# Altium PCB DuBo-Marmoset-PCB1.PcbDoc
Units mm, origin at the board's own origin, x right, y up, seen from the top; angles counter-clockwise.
Board outline 13.9 x 25.08 mm, 4 copper layers (Top Signal, Layer 2 - VCC, Layer 3 - GND, Bottom Layer), stack 0.532 mm thick; 7 components, 33 nets, 180 pads, 39 vias.
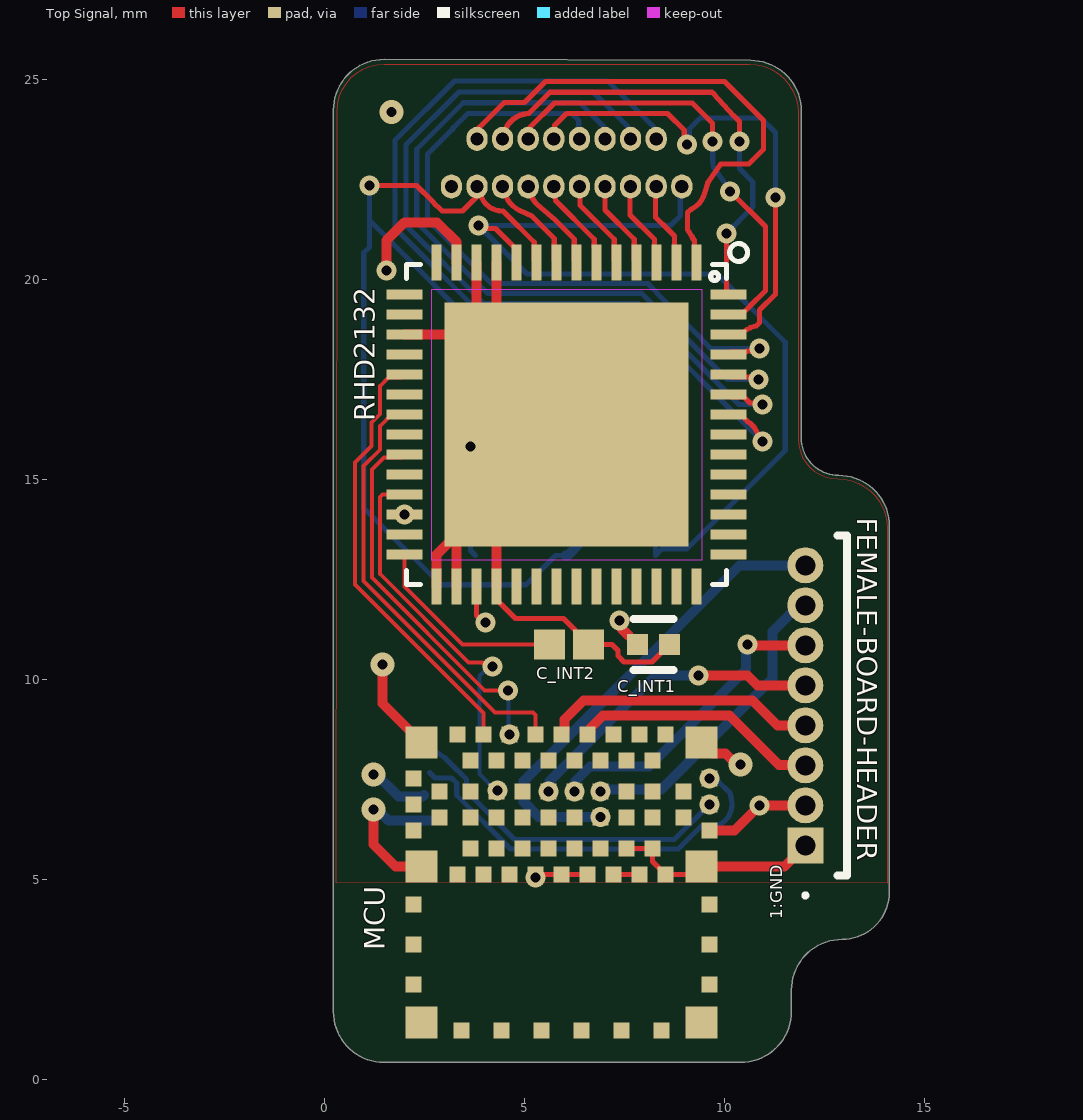
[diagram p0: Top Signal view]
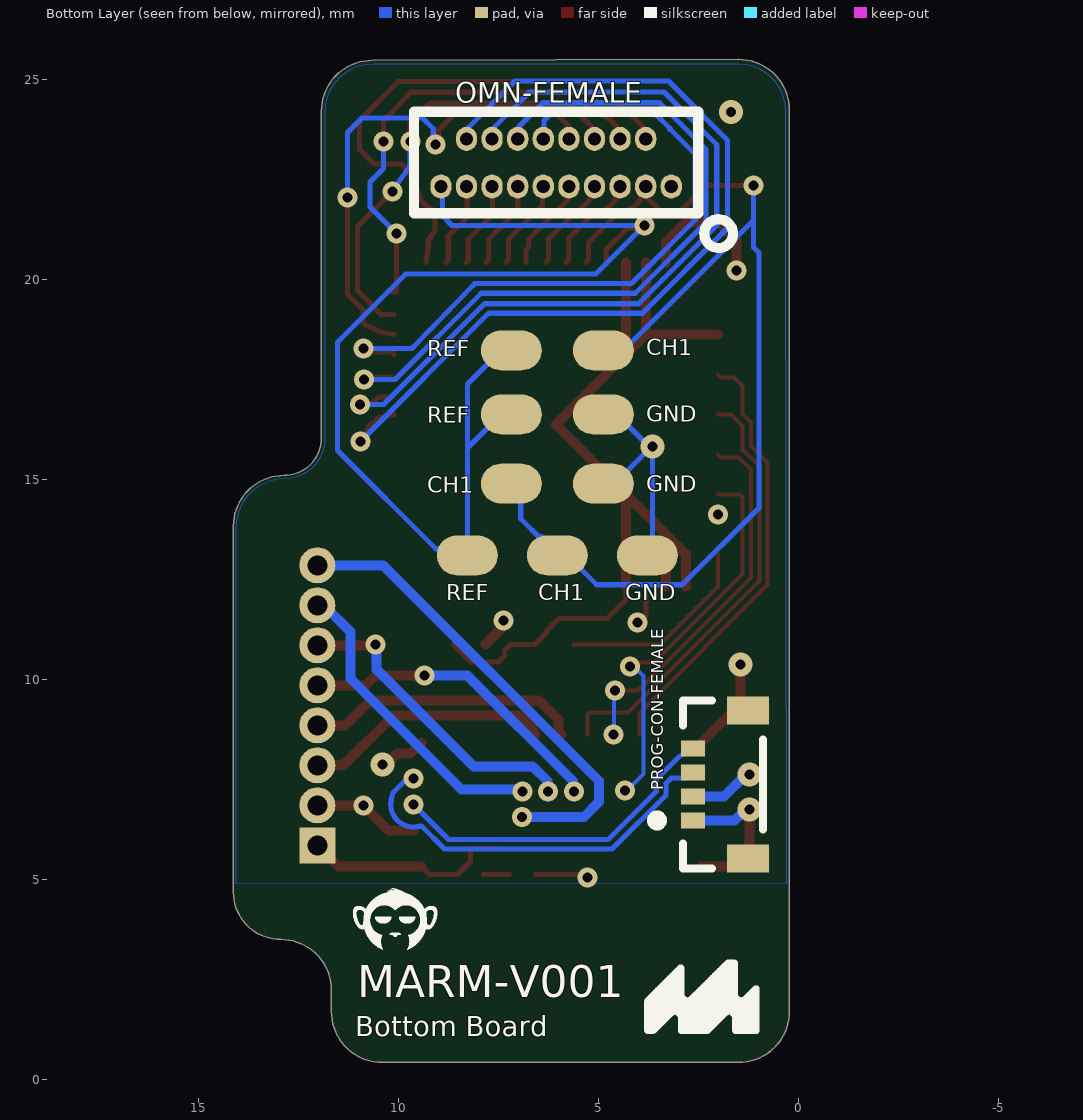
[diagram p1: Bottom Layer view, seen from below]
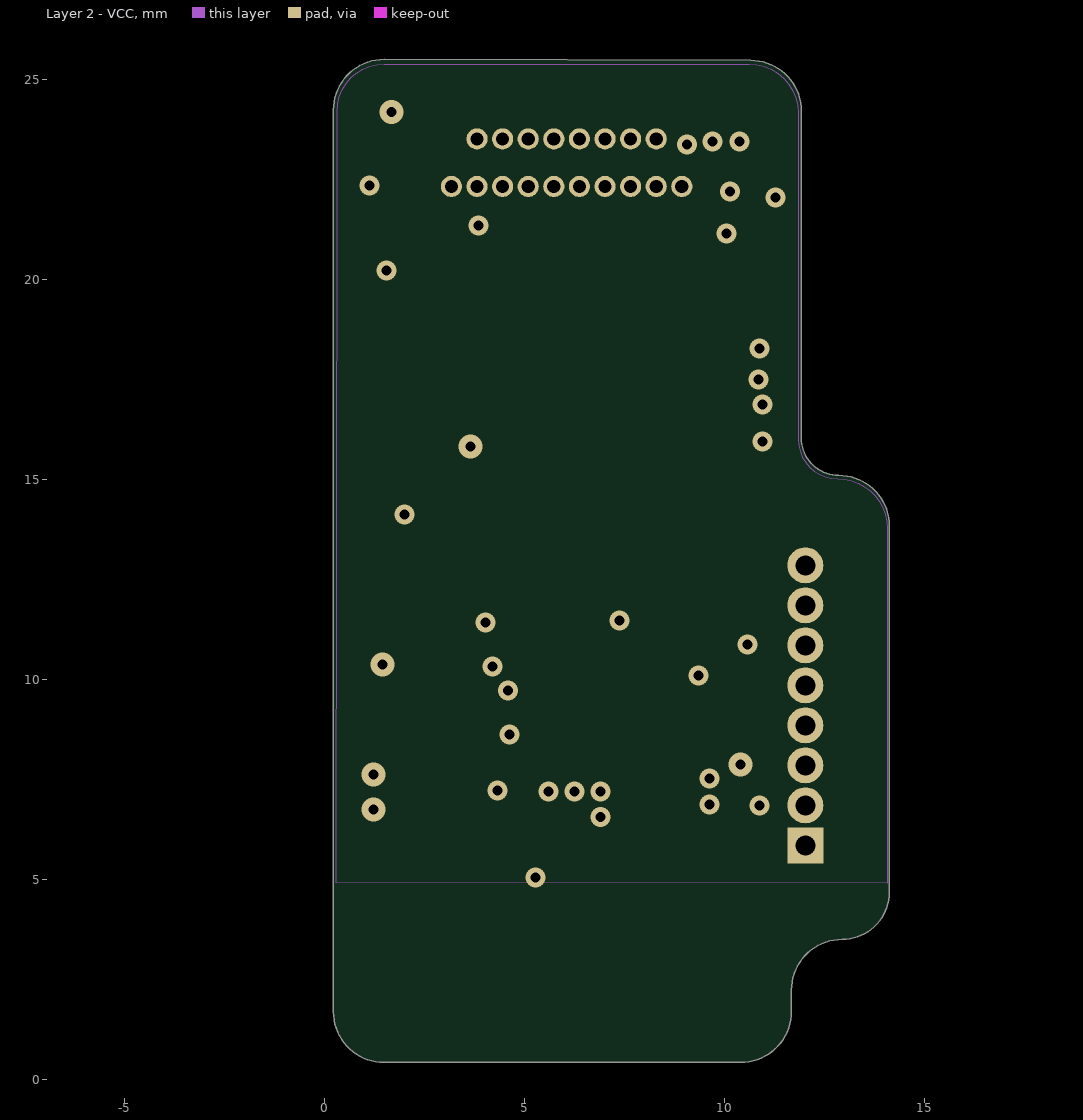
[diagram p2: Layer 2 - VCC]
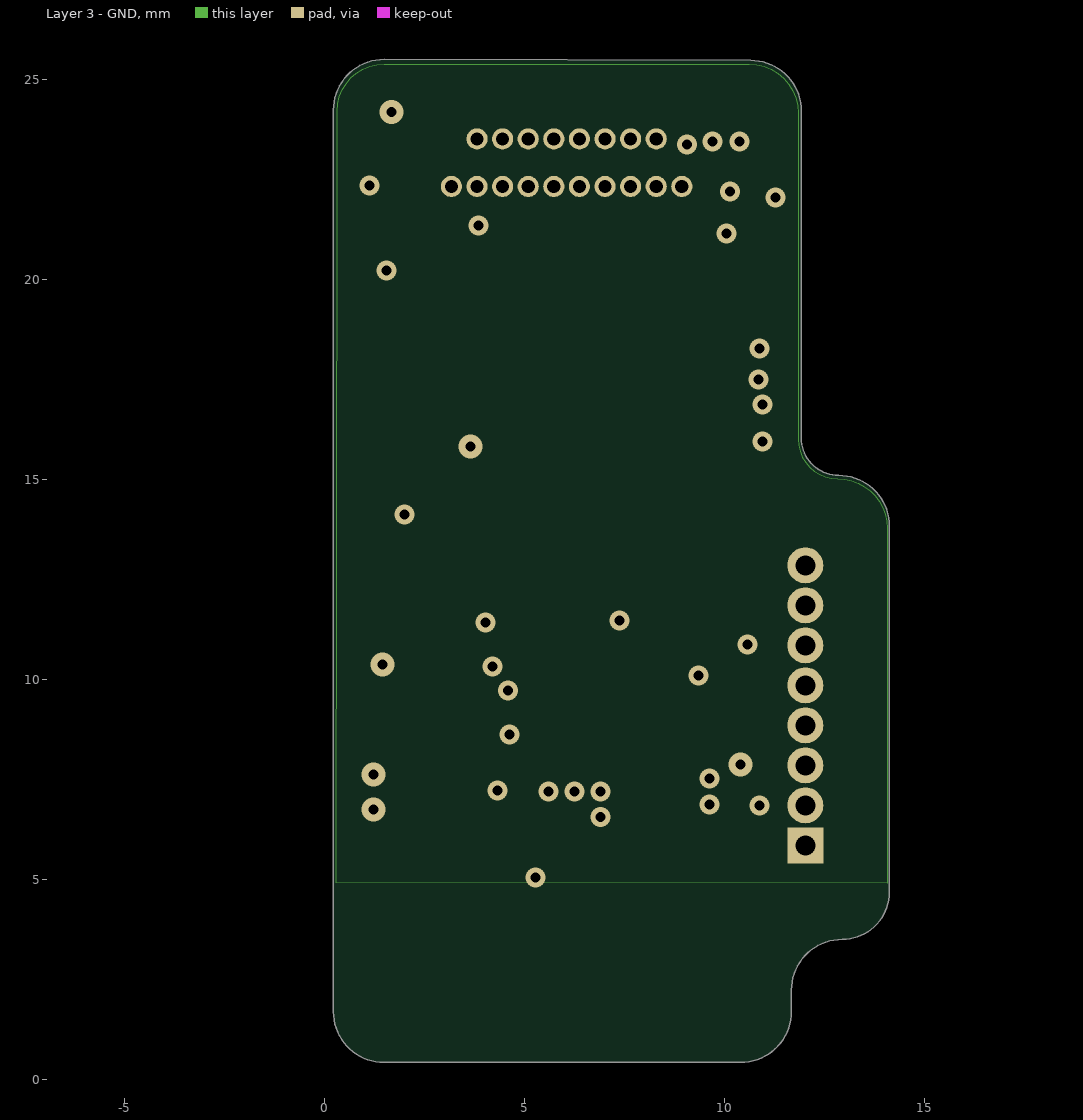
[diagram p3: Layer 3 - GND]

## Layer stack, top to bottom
Top Solder: solder mask 0.012, FC-001, Dk 4
Top Solder: solder mask 0.0102, Solder Resist, Dk 3.5
Top Signal: signal copper 0.0175
Dielectric 2: prepreg 0.0711, PP-006, Dk 4.1
Layer 2 - VCC: signal copper 0.0175
Dielectric 1: dielectric 0.32, FR-4, Dk 4.8
Layer 3 - GND: signal copper 0.0175
Dielectric 3: prepreg 0.0711, PP-006, Dk 4.1
Bottom Layer: signal copper 0.0175
Flex Bottom Coverlay: solder mask 0.0102, Solder Resist, Dk 3.5
Flex Bottom Coverlay: solder mask 0.012, FC-001, Dk 4

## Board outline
1.495,0.425 cw(c1.495,1.695) 0.225,1.695 0.225,24.23 cw(c1.495,24.23) 1.495,25.5 1.5,25.5 10.655,25.475 cw(c10.655,24.205) 11.925,24.205 11.925,16.03 ccw(c12.855,16.03) 12.855,15.1 cw(c12.855,13.83) 14.125,13.83 14.125,4.68 cw(c12.945,4.68) 12.945,3.5 ccw(c12.945,2.23) 11.675,2.23 11.675,1.695 cw(c10.405,1.695) 10.405,0.425

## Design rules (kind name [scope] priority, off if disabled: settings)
Clearance Eurocircuits [All] p1: gap=0.25 ignorepadtopadclearanceinfootprint=TRUE except(0.11: Arc-Arc Arc-Track Arc-SMDPad Arc-Via Track-Track Track-SMDPad Track-Via SMDPad-SMDPad SMDPad-Via; 0.125: Arc-Hole Track-Hole SMDPad-Hole THPad-Hole Via-Hole Fill-Hole Poly-Hole Region-Hole Text-Hole; 0.13: THPad-THPad Via-Via) // Marmoset Project
Clearance [All] p2: gap=0.254 ignorepadtopadclearanceinfootprint=FALSE
DiffPairsRouting [All] p1: maxlimit=0.254 minlimit=0.254 mostfreqgap=0.254 substack1={4CFAFDA6-F42D-4065-9748-95331561A070} toplayer_{4cfafda6-f42d-4065-9748-95331561a070}_minwidth=0.381 toplayer_{4cfafda6-f42d-4065-9748-95331561a070}_maxwidth=0.381 toplayer_{4cfafda6-f42d-4065-9748-95331561a070}_prefwidth=0.381 midlayer1_{4cfafda6-f42d-4065-9748-95331561a070}_minwidth=0.381 midlayer1_{4cfafda6-f42d-4065-9748-95331561a070}_maxwidth=0.381 midlayer1_{4cfafda6-f42d-4065-9748-95331561a070}_prefwidth=0.381 midlayer2_{4cfafda6-f42d-4065-9748-95331561a070}_minwidth=0.381 midlayer2_{4cfafda6-f42d-4065-9748-95331561a070}_maxwidth=0.381 midlayer2_{4cfafda6-f42d-4065-9748-95331561a070}_prefwidth=0.381 bottomlayer_{4cfafda6-f42d-4065-9748-95331561a070}_minwidth=0.381 bottomlayer_{4cfafda6-f42d-4065-9748-95331561a070}_maxwidth=0.381 bottomlayer_{4cfafda6-f42d-4065-9748-95331561a070}_prefwidth=0.381 toplayer_minwidth=0.381 toplayer_maxwidth=0.381 toplayer_prefwidth=0.381 midlayer1_minwidth=0.381 midlayer1_maxwidth=0.381 midlayer1_prefwidth=0.381 midlayer2_minwidth=0.381 midlayer2_maxwidth=0.381 midlayer2_prefwidth=0.381 bottomlayer_minwidth=0.381 bottomlayer_maxwidth=0.381 bottomlayer_prefwidth=0.381 maxuncoupledlength=12.7
PolygonConnect [All] p1: connectstyle=Relief reliefconductorwidth=0.254 reliefentries=4 polygonreliefangle="90 Angle" airgapwidth=0.254
RoutingVias [All] p1: holewidth=0.12 width=0.5 viastyle="Through Hole" minholewidth=0.1 minwidth=0.45 maxholewidth=0.15 maxwidth=0.6
SolderMaskExpansion [All] p1: expansion=0.102 istentingtop=FALSE
SupplyNets "Schematic Supply Nets_3" [InNet('GND')] p1: voltage=0.000
Width Width_1 [All] p1: maxlimit=0.26 minlimit=0.09 preferedwidth=0.13 substack1={4CFAFDA6-F42D-4065-9748-95331561A070} toplayer_{4cfafda6-f42d-4065-9748-95331561a070}_minwidth=0.254 toplayer_{4cfafda6-f42d-4065-9748-95331561a070}_maxwidth=0.254 toplayer_{4cfafda6-f42d-4065-9748-95331561a070}_prefwidth=0.254 midlayer1_{4cfafda6-f42d-4065-9748-95331561a070}_minwidth=0.254 midlayer1_{4cfafda6-f42d-4065-9748-95331561a070}_maxwidth=0.254 midlayer1_{4cfafda6-f42d-4065-9748-95331561a070}_prefwidth=0.254 midlayer2_{4cfafda6-f42d-4065-9748-95331561a070}_minwidth=0.2 midlayer2_{4cfafda6-f42d-4065-9748-95331561a070}_maxwidth=0.254 midlayer2_{4cfafda6-f42d-4065-9748-95331561a070}_prefwidth=0.25 bottomlayer_{4cfafda6-f42d-4065-9748-95331561a070}_minwidth=0.2 bottomlayer_{4cfafda6-f42d-4065-9748-95331561a070}_maxwidth=0.3 bottomlayer_{4cfafda6-f42d-4065-9748-95331561a070}_prefwidth=0.25 minimp=50.000000 maximp=50.000000 favimp=50.000000
29 further rules are at their usual default settings.

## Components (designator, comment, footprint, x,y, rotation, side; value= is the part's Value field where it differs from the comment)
C_INT1 "C0402C104K8PACTU" FP-C0402-BB-MFG 8.227,10.872 r0 top value="0.10 μF"
C_INT2 "04023C103JAT2A" CAPC1005X56X25ML10T15 6.117,10.872 r0 top
FEMALE-BOARD-HEADER "8POS 1.0MM PITCH SOCKET, SIL, TH - BC065-08-A-L-D" FEMALE-BOARD-HEADER-8 12.025,5.85 r90 top
MCU "ISP1807" ISP1807-LR 1.925,8.925 r0 top
OMN-FEMALE "OMNETICS_A79038-001" OMNETICS_A79038-001_Footprint 6.057,22.922 r180 bottom
PROG-CON-FEMALE "SM04B-XSRS-ETB (LF)(SN)" FP-SM04B-XSRS-ETB_LF_SN-MFG 1.882,7.372 r90 bottom
RHD2132 "Intan Technologies RHD2132 chip" QFN56_8_X_8_LARGE 6.057,16.372 r270 top

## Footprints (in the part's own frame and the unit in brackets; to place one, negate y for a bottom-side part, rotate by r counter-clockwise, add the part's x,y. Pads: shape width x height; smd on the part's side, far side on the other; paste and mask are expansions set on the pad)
CAPC1005X56X25ML10T15 [mm] "Chip Capacitor, 2-Leads, Body 1.00x0.50mm, IPC Low Density"
  rect 0.78x0.74 smd: 1(-0.49,0) 2(0.49,0)
  body extent -0.55,-0.3 0.55,0.3, height 0.56
FEMALE-BOARD-HEADER-8 [mm]
  rect 0.9x0.9 hole 0.5: 1(0,0)
  round 0.9 hole 0.5: 2(1,0) 3(2,0) 4(3,0) 5(4,0) 6(5,0) 7(6,0) 8(7,0)
  silkscreen extent -1.3,-1.04 7.75,0.05, body extent -0.75,-1 7.75,0.5, height 2.1
FP-C0402-BB-MFG [mm]
  rect 0.52x0.52 smd paste+0 mask+0: 1(-0.4,0) 2(0.4,0)
  silkscreen extent -0.5,-0.64 0.5,0.64, body extent -0.5,-0.25 0.5,0.25, height 0.55
FP-SM04B-XSRS-ETB_LF_SN-MFG [mm]
  rect 0.4x0.6 smd paste+0 mask+0: 1(-0.9,0.75) 2(-0.3,0.75) 3(0.3,0.75) 4(0.9,0.75)
  rect 0.7x1.05 smd paste+0 mask+0: 5(-1.85,-0.625) 6(1.85,-0.625)
  silkscreen extent -2.1,-1 2.1,1.78, body extent -2.1,-1 2.1,1, height 1.45
ISP1807-LR [mm] "Insight SiP BLE module all pins"
  rect 0.8x0.8 smd mask+0.05: 1(0.5,-0.5) 7(0.5,-3.6) 25(7.5,-3.6) 31(7.5,-0.5) 68(0.5,-7.5) 75(7.5,-7.5)
  rect 0.4x0.4 smd mask+0.05: 2(0.3,-1.4) 3(0.95,-1.725) 4(0.3,-2.05) 5(0.95,-2.375) 6(0.3,-2.7) 8(1.4,-3.8) 9(1.725,-3.15) 10(2.05,-3.8) 11(2.375,-3.15) 12(2.7,-3.8) 13(3.025,-3.15) 14(3.35,-3.8) 15(3.675,-3.15) 16(4,-3.8) 17(4.325,-3.15) 18(4.65,-3.8) 19(4.975,-3.15) 20(5.3,-3.8) 21(5.625,-3.15) 22(5.95,-3.8) 23(6.275,-3.15) 24(6.6,-3.8) 26(7.7,-2.7) 27(7.05,-2.375) 28(7.7,-2.05) 29(7.05,-1.725) 30(7.7,-1.4) 32(6.6,-0.3) 33(6.275,-0.95) 34(5.95,-0.3) 35(5.625,-0.95) 36(5.3,-0.3) 37(4.975,-0.95) 38(4.65,-0.3) 39(4.325,-0.95) 40(4,-0.3) 41(3.675,-0.95) 42(3.35,-0.3) 43(3.025,-0.95) 44(2.7,-0.3) 45(2.375,-0.95) 46(2.05,-0.3) 47(1.725,-0.95) 48(1.4,-0.3) 49(6.275,-1.725) 50(5.625,-1.725) 51(4.975,-1.725) 52(4.325,-1.725) 53(3.675,-1.725) 54(3.025,-1.725) 55(2.375,-1.725) 56(1.725,-1.725) 57(6.275,-2.375) 58(5.625,-2.375) 59(4.975,-2.375) 60(4.325,-2.375) 61(3.675,-2.375) 62(3.025,-2.375) 63(2.375,-2.375) 64(1.725,-2.375) 65(0.3,-4.55) 66(0.3,-5.55) 67(0.3,-6.55) 69(1.5,-7.701) 70(2.5,-7.701) 71(3.5,-7.701) 72(4.5,-7.701) 73(5.5,-7.701) 74(6.5,-7.701) 76(7.7,-6.55) 77(7.7,-5.55) 78(7.7,-4.55)
  Top Signal pour cut-out: 8.1,0.1 8.1,-4.05 16,-4.05 16,-8.5 -8,-8.5 -8,-4.05 -0.1,-4.05 -0.1,0.1
  body extent 0,-8 8,0.01, height 1.2
OMNETICS_A79038-001_Footprint [mm]
  oval 0.53x0.6 / inner round 0.53 / far side oval 0.53x0.6 hole 0.33 paste-2539.97 mask+0: 1(2.88,-0.6) 2(2.24,-0.6) 3(1.6,-0.6) 4(0.96,-0.6) 5(0.32,-0.6) 6(-0.32,-0.6) 7(-0.96,-0.6) 8(-1.6,-0.6) 9(-2.24,-0.6) 10(-2.88,-0.6) 11(2.24,0.591) 12(1.6,0.591) 13(0.96,0.591) 14(0.32,0.591) 15(-0.32,0.591) 16(-0.96,0.591) 17(-1.6,0.591) 18(-2.24,0.591)
  silkscreen extent -3.56,-2.14 4.42,1.27, body extent -3.37,-0.89 3.37,0.9, height 4.61
QFN56_8_X_8_LARGE [mm]
  rect 0.9x0.25 smd: 1(-4.05,3.25) 2(-4.05,2.75) 3(-4.05,2.25) 4(-4.05,1.75) 5(-4.05,1.25) 6(-4.05,0.75) 7(-4.05,0.25) 8(-4.05,-0.25) 9(-4.05,-0.75) 10(-4.05,-1.25) 11(-4.05,-1.75) 12(-4.05,-2.25) 13(-4.05,-2.75) 14(-4.05,-3.25) 29(4.05,-3.25) 30(4.05,-2.75) 31(4.05,-2.25) 32(4.05,-1.75) 33(4.05,-1.25) 34(4.05,-0.75) 35(4.05,-0.25) 36(4.05,0.25) 37(4.05,0.75) 38(4.05,1.25) 39(4.05,1.75) 40(4.05,2.25) 41(4.05,2.75) 42(4.05,3.25)
  rect 0.25x0.9 smd: 15(-3.25,-4.05) 16(-2.75,-4.05) 17(-2.25,-4.05) 18(-1.75,-4.05) 19(-1.25,-4.05) 20(-0.75,-4.05) 21(-0.25,-4.05) 22(0.25,-4.05) 23(0.75,-4.05) 24(1.25,-4.05) 25(1.75,-4.05) 26(2.25,-4.05) 27(2.75,-4.05) 28(3.25,-4.05) 43(3.25,4.05) 44(2.75,4.05) 45(2.25,4.05) 46(1.75,4.05) 47(1.25,4.05) 48(0.75,4.05) 49(0.25,4.05) 50(-0.25,4.05) 51(-0.75,4.05) 52(-1.25,4.05) 53(-1.75,4.05) 54(-2.25,4.05) 55(-2.75,4.05) 56(-3.25,4.05)
  rect 6.1x6.1 smd: CENTER(0,0)
  Top Signal keep-out region: -3.375,-3.375 -3.375,3.375 3.4,3.375 3.4,-3.375
  silkscreen extent -4.52,-4 4,4.52, body extent -4.5,-4.5 4.5,4.5, height 0.85

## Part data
C_INT1: library part CMP-2008-02046-2, "CAP CER 0.1UF 10V X5R 0402", Capacitance="0.10 μF", Manufacturer=Kemet, Package=C0402-BB, Temperature="-55°C to +125°C", Temperature Characteristic=X5R, Temperature Coefficient=15%, Temperature Range High=+125°C, Temperature Range Low=-55°C, Tolerance=0.1, Voltage Rating="10 V"
C_INT2: library part CMP-2008-02925-1, Manufacturer="AVX Interconnect / Elco"
FEMALE-BOARD-HEADER: library part FEMALE-BOARD-HEADER-8, Supplier Part Number 1=2073-BC065-08-A-L-D-ND
MCU: library part ISP1807-LR, "ISP Smart Bluetooth Module"
OMN-FEMALE: "18 PIN FEMALE NANO DUAL ROW CONNECTOR W/GUIDE POST HOLES"
PROG-CON-FEMALE: library part CMP-17439-000402-2, "CONN HEADER SMD R/A 4POS 0.6MM", Current Rating=200mA, Flammability Rating="UL94 V-0", Insulation Color=Natural, Max Operating Temperature=85°C, Min Operating Temperature=-25°C, Voltage Rating=30V
RHD2132: library part RHD2132_QFN, Package=QFN56_8_X_8_LARGE

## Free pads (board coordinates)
  oval 1.524x1 smd far side: 16(3.775,13.1) 16(4.875,14.892) 16(4.875,16.625) 16(4.875,18.225) 16(6.025,13.1) 16(7.175,14.892) 16(7.175,16.625) 16(7.175,18.225) 16(8.275,13.1)

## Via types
v1: diameter 0.5, hole 0.25, Top Signal to Bottom Layer, 30 vias
v2: diameter 0.6, hole 0.25, Top Signal to Bottom Layer, 6 vias
v3: diameter 0.5, hole 0.25, Layer 3 - GND to Bottom Layer, 3 vias

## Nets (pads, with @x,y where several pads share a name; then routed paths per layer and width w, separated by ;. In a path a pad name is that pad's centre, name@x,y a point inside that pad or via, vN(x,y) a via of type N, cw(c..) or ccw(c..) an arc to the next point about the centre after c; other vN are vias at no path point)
BAT_TEMP: FEMALE-BOARD-HEADER.3 MCU.38 | length 6.2
  Top Signal w0.13: FEMALE-BOARD-HEADER.3@11.943,7.85 FEMALE-BOARD-HEADER.3
  Top Signal w0.25: MCU.38 6.65,8.7 6.65,8.782 6.968,9.1 10.125,9.1 11.367,7.858 11.935,7.858 FEMALE-BOARD-HEADER.3@11.943,7.85
GND: C_INT1.2 C_INT2.2 FEMALE-BOARD-HEADER.1 MCU.1 MCU.7 MCU.14 MCU.16 MCU.18 MCU.21 MCU.23 MCU.24 MCU.25 MCU.31 OMN-FEMALE.1 pad.16@3.775,13.1 pad.16@4.875,14.892 pad.16@4.875,16.625 PROG-CON-FEMALE.1 RHD2132.11 RHD2132.12 RHD2132.17 RHD2132.29 RHD2132.30 RHD2132.32 RHD2132.CENTER | length 43.6
  Top Signal w0.13: RHD2132.32 4.307,11.997 4.779,11.525 5.981,11.525 6.282,11.224 6.282,11.177 6.587,10.872 C_INT2.2 7.192,10.872 7.343,10.721 7.343,10.588 7.495,10.437 8.192,10.437 C_INT1.2 ; v1(5.275,5.05) MCU.14 MCU.16 MCU.18 ; MCU.21 MCU.23 8.2,5.45 MCU.24 9.225,5.125 MCU.25
  Top Signal w0.25: v2(1.225,6.75) 1.225,5.875 1.775,5.325 MCU.7 ; v2(1.45,10.375) 1.45,9.4 MCU.1 ; RHD2132.17 RHD2132.CENTER@3.807,18.622 ; RHD2132.29 2.807,13.122 RHD2132.CENTER@3.307,13.622 ; RHD2132.30 RHD2132.CENTER@3.307,13.622 ; RHD2132.12 RHD2132.CENTER@3.807,18.622 ; RHD2132.32 RHD2132.CENTER@4.307,14.622 ; RHD2132.11 RHD2132.CENTER@4.307,18.122 ; MCU.25 11.5,5.325 FEMALE-BOARD-HEADER.1 ; MCU.31 9.7,8.15 10.026,8.15 10.303,7.873 v2(10.398,7.873) ; RHD2132.CENTER@3.307,13.622 RHD2132.CENTER@4.307,14.622 ; RHD2132.CENTER@3.807,18.622 RHD2132.CENTER@4.307,18.122 ; RHD2132.CENTER@4.307,14.622 RHD2132.CENTER RHD2132.CENTER@4.307,18.122
  Bottom Layer w0.13: pad.16@3.775,13.1 3.65,13.225 v2(3.65,15.825) v2@3.665,15.825 ; pad.16@4.875,14.892 4.598,14.892 v2@3.665,15.825 ; pad.16@4.875,16.625 4.531,16.625 3.732,15.825 v2@3.665,15.825
  Bottom Layer w0.25: v2(1.225,6.75) 1.32,6.75 1.598,6.472 PROG-CON-FEMALE.1
  other v2: 1.68,24.181
INT0: OMN-FEMALE.2 pad.16@4.875,18.225 pad.16@6.025,13.1 pad.16@7.175,14.892 RHD2132.9 | length 27.5
  Top Signal w0.13: v1(1.125,22.35) 2.305,22.35 2.698,21.957 2.726,21.922 ccw(c3.177,22.287) 2.811,21.837 2.846,21.809 2.911,21.744 2.949,21.706 3.45,21.706 3.815,22.07 OMN-FEMALE.2@3.815,22.172 ; OMN-FEMALE.2 3.837,22.302 3.877,22.24 OMN-FEMALE.2@3.884,22.194 ; OMN-FEMALE.2@3.884,22.194 ccw(c4.457,22.287) 4.457,21.707 4.466,21.707 4.502,21.671 5.247,20.926 5.247,20.482 RHD2132.9
  Bottom Layer w0.13: v1(1.125,22.35) 1.125,21.478 ; pad.16@4.875,18.225 4.378,18.225 1.125,21.478 ; pad.16@6.025,13.1 5.775,13.1 5.04,12.365 2.908,12.365 0.985,14.288 0.985,20.664 1.125,20.804 1.125,21.478 ; pad.16@6.431,13.506 6.942,14.017 pad.16@6.942,14.658
  Bottom Layer w0.25: pad.16@6.025,13.1 6.084,13.1 6.431,13.446 pad.16@6.431,13.506 ; pad.16@6.942,14.658 pad.16@7.175,14.892
  other v3: 1.125,22.35
INT1: OMN-FEMALE.3 RHD2132.8 | length 2.5
  Top Signal w0.13: OMN-FEMALE.3@4.47,22.325 4.509,22.172 ccw(c5.173,22.343) 4.885,21.721 5.187,21.581 5.204,21.565 5.747,21.021 5.747,20.482 RHD2132.8
INT2: OMN-FEMALE.4 RHD2132.7 | length 2.4
  Top Signal w0.13: OMN-FEMALE.4@5.105,22.325 5.144,22.172 5.144,22.106 5.233,21.976 ccw(c5.74,22.325) 5.337,21.86 5.757,21.496 5.764,21.49 6.247,21.007 6.247,20.482 RHD2132.7
INT3: OMN-FEMALE.5 RHD2132.6 | length 2.3
  Top Signal w0.13: OMN-FEMALE.5@5.74,22.325 5.74,22.147 5.779,22.108 5.779,21.971 6.747,21.002 6.747,20.883 6.747,20.807 6.807,20.747 RHD2132.6
INT4\: OMN-FEMALE.6 RHD2132.5 | length 2.3
  Top Signal w0.13: OMN-FEMALE.6@6.375,22.325 6.395,22.305 6.395,21.855 7.247,21.002 7.247,20.482 RHD2132.5
INT5: OMN-FEMALE.7 RHD2132.4 | length 2.2
  Top Signal w0.13: OMN-FEMALE.7@7.01,22.325 7.016,22.319 7.016,21.734 7.747,21.002 7.747,20.883 7.747,20.482 RHD2132.4
INT6: OMN-FEMALE.8 RHD2132.3 | length 2.2
  Top Signal w0.13: OMN-FEMALE.8@7.645,22.325 7.645,21.612 8.252,21.005 8.252,20.477 RHD2132.3
INT7: OMN-FEMALE.9 RHD2132.2 | length 2.1
  Top Signal w0.13: OMN-FEMALE.9@8.28,22.325 8.28,21.554 8.588,21.245 8.752,21.081 8.752,20.477 RHD2132.2@8.804,20.425
INT8: OMN-FEMALE.11 RHD2132.1 | length 13
  Top Signal w0.13: OMN-FEMALE.11@3.835,23.519 3.85,23.534 3.85,23.776 4.496,24.422 5.002,24.422 5.529,24.949 10.001,24.949 10.975,23.975 10.975,23.251 10.609,22.885 9.909,22.885 9.597,22.435 9.585,22.418 9.503,22.147 cw(c8.915,22.325) 9.477,22.077 9.473,22.067 cw(c8.937,22.287) 9.217,21.78 9.175,21.757 9.158,21.745 9.082,21.669 9.082,21.642 9.082,21.233 9.195,21.061 ; 9.252,20.966 9.252,20.802 RHD2132.1
  Top Signal w0.14: 9.195,21.061 ccw(c9.712,21.302) 9.252,20.966
INT9: OMN-FEMALE.12 RHD2132.56 | length 11.5
  Top Signal w0.13: OMN-FEMALE.12@4.47,23.519 OMN-FEMALE.12@4.499,23.653 ; 4.988,24.128 5.114,24.152 5.641,24.679 9.694,24.679 9.734,24.639 10.232,24.093 10.375,23.95 v1(10.375,23.45) ; v1(10.05,21.15) 10.05,19.682 RHD2132.56@10.126,19.677
  Top Signal w0.14: OMN-FEMALE.12@4.499,23.653 cw(c5.105,23.519) 4.988,24.128
  Bottom Layer w0.13: v1(10.05,21.15) 10.709,21.809 10.709,22.437 10.375,22.77 v1(10.375,23.45)
INT10: OMN-FEMALE.13 RHD2132.55 | length 11.2
  Top Signal w0.13: OMN-FEMALE.13@5.105,23.519 5.12,23.534 5.12,23.776 5.753,24.409 9.196,24.409 9.7,23.904 v1(9.7,23.446) ; RHD2132.55 10.432,19.122 10.638,19.328 10.638,19.331 11.025,19.717 11.025,21.321 v1(10.144,22.203)
  Bottom Layer w0.13: v1(9.7,23.446) 9.71,22.939 ccw(c10.275,22.95) 9.732,22.794 10.151,22.208 v1(10.144,22.203) v1(10.144,22.203)
INT11: OMN-FEMALE.14 RHD2132.54 | length 12.9
  Top Signal w0.13: OMN-FEMALE.14@5.74,23.519 5.755,23.534 5.755,23.845 6.057,24.147 8.582,24.147 8.996,23.733 8.996,23.446 v1(9.066,23.375) ; RHD2132.54 10.483,18.682 cw(c10.875,18.275) 10.738,18.823 10.802,18.839 10.878,18.915 10.878,19.231 11.275,19.628 v1(11.275,22.05)
  Bottom Layer w0.13: v1(9.066,23.375) 9.128,23.437 9.128,23.765 9.399,24.036 10.911,24.036 11.275,23.672 v1(11.275,22.05)
INT12: OMN-FEMALE.15 RHD2132.53 | length 16.9
  Top Signal w0.13: RHD2132.53 10.167,18.182 10.538,18.182 10.568,18.213 10.813,18.213 v1(10.875,18.275)
  Bottom Layer w0.13: 3.205,23.752 2.58,23.127 2.58,21.489 4.174,19.894 8.088,19.894 8.127,19.855 9.618,18.314 9.656,18.275 v1(10.875,18.275) ; 3.215,23.776 3.586,24.147 6.182,24.147 6.359,23.97 6.359,23.534 OMN-FEMALE.15@6.375,23.519
  Bottom Layer w0.14: 3.205,23.752 ccw(c3.181,23.776) 3.215,23.776
INT13: OMN-FEMALE.16 RHD2132.52 | length 18.4
  Top Signal w0.13: RHD2132.52@10.167,17.562 10.788,17.562 v1(10.853,17.497)
  Bottom Layer w0.13: OMN-FEMALE.16@7.01,23.519 6.994,23.534 6.994,23.808 6.385,24.417 3.474,24.417 2.31,23.253 2.31,21.419 4.077,19.652 7.927,19.652 10.082,17.497 v1(10.853,17.497)
INT14: OMN-FEMALE.17 RHD2132.51 | length 20.4
  Top Signal w0.13: RHD2132.51@10.167,17.062 10.492,17.062 10.644,16.91 10.917,16.91 v1(10.956,16.872)
  Bottom Layer w0.13: OMN-FEMALE.17@7.645,23.519 7.629,23.534 7.629,23.776 7.266,24.139 6.718,24.687 3.362,24.687 2.04,23.364 2.04,21.35 3.997,19.392 7.847,19.392 10.368,16.872 v1(10.956,16.872)
INT15: OMN-FEMALE.18 RHD2132.50 | length 22.6
  Top Signal w0.13: RHD2132.50 10.48,16.562 ccw(c10.95,16.875) 10.663,16.388 10.732,16.32 v1(10.95,15.95)
  Bottom Layer w0.13: OMN-FEMALE.18@8.28,23.519 8.264,23.534 8.264,23.776 7.083,24.957 3.25,24.957 1.77,23.476 1.77,21.28 3.898,19.152 7.748,19.152 v1(10.95,15.95)
INT_CS: MCU.46 RHD2132.19 | length 11
  Top Signal w0.1: RHD2132.19 1.932,17.547 1.607,17.547 1.397,17.337 1.397,16.637 1.182,16.422 1.182,15.832 0.767,15.417 0.767,12.373 3.975,9.165 MCU.46
INT_MISO: MCU.55 RHD2132.25 | length 9.8
  Top Signal w0.1: RHD2132.25 1.456,14.622 1.397,14.563 1.397,12.634 3.609,10.422 3.948,10.422 3.972,10.399 4.13,10.399 v1(4.207,10.322)
  Bottom Layer w0.1: v1(4.207,10.322) 4.107,10.322 3.875,10.09 3.875,7.629 4.284,7.22 v1(4.33,7.22)
INT_MOSI: MCU.44 RHD2132.23 | length 9.4
  Top Signal w0.1: RHD2132.23 1.932,15.547 1.491,15.547 1.187,15.243 1.187,12.547 4.009,9.724 v1(4.589,9.724)
  Bottom Layer w0.1: v1(4.589,9.724) 4.607,9.707 4.607,8.643 v1(4.625,8.625)
INT_REF: OMN-FEMALE.10 pad.16@7.175,16.625 pad.16@7.175,18.225 pad.16@8.275,13.1 RHD2132.10 | length 30.7
  Top Signal w0.13: v1(3.852,21.346) 3.922,21.275 4.279,21.275 4.807,20.747 RHD2132.10 ; OMN-FEMALE.10@8.877,22.538 8.915,22.5 OMN-FEMALE.10@8.915,22.325
  Bottom Layer w0.13: pad.16@7.175,18.225 7.437,18.225 8.275,17.387 8.275,15.787 ; pad.16@7.437,16.625 8.275,15.787 ; OMN-FEMALE.10@8.907,22.325 8.899,22.318 8.899,21.59 8.656,21.346 3.913,21.346 v1(3.852,21.346) 5.063,20.134 9.815,20.134 11.521,18.428 11.521,15.722 9.065,13.266 8.441,13.266 8.275,13.1 8.275,15.787
  Bottom Layer w0.25: pad.16@7.175,16.625 pad.16@7.437,16.625
INT_SCLK: MCU.42 RHD2132.21 | length 11
  Top Signal w0.1: RHD2132.21 1.682,16.622 1.397,16.337 1.397,15.75 0.977,15.33 0.977,12.46 3.922,9.514 4.265,9.172 4.568,9.172 cw(c4.625,8.625) 4.682,9.172 5.216,9.172 5.246,9.143 5.275,9.113 MCU.42
NetC_INT2_1: C_INT2.1 RHD2132.28 | length 5
  Top Signal w0.1: RHD2132.28 2.007,12.321 3.456,10.872 C_INT2.1
NetMCU_20: MCU.20 MCU.22 | length 0.7
  Top Signal w0.13: MCU.20 MCU.22
SDHC_CS: FEMALE-BOARD-HEADER.8 MCU.59 | length 11.9
  Top Signal w0.25: MCU.59 6.907,6.543 v1(6.907,6.562)
  Bottom Layer w0.25: v1@6.917,6.572 v1(6.907,6.562) 5.358,6.562 4.982,6.938 4.982,7.456 10.376,12.85 FEMALE-BOARD-HEADER.8
SDHC_MISO: FEMALE-BOARD-HEADER.6 MCU.52 | length 7.8
  Top Signal w0.25: MCU.52 6.253,7.197 v1(6.257,7.197) ; v1(10.575,10.875) 10.6,10.85 FEMALE-BOARD-HEADER.6
  Bottom Layer w0.25: v1(6.257,7.197) 6.275,7.215 6.275,7.459 6.641,7.825 8.116,7.825 10.541,10.25 10.541,10.841 v1(10.575,10.875)
  other v3: 10.575,10.875
SDHC_MOSI: FEMALE-BOARD-HEADER.5 MCU.53 | length 7.9
  Top Signal w0.25: v3(9.35,10.1) 10.575,10.1 10.825,9.85 FEMALE-BOARD-HEADER.5
  Bottom Layer w0.25: v1(5.607,7.197) 5.632,7.222 5.632,7.456 8.276,10.1 v3(9.35,10.1)
  other v1: 9.35,10.1
SDHC_SCLK: FEMALE-BOARD-HEADER.7 MCU.51 | length 7.7
  Bottom Layer w0.25: v1(6.9,7.2) 6.948,7.248 8.423,7.248 11.2,10.025 11.2,11.192 11.858,11.85 FEMALE-BOARD-HEADER.7
SWDCLK: MCU.30 PROG-CON-FEMALE.3 | length 10
  Bottom Layer w0.13: PROG-CON-FEMALE.3 2.767,7.537 3.175,7.537 3.31,7.402 3.31,7.102 4.655,5.757 8.846,5.757 9.417,6.327 9.471,6.327 9.486,6.327 ccw(c9.625,6.875) 10.178,6.99 10.171,7.022 10.136,7.163 10.117,7.182 9.845,7.454 9.696,7.454 v1(9.625,7.525)
SWDIO: MCU.28 PROG-CON-FEMALE.4 | length 8.4
  Bottom Layer w0.13: PROG-CON-FEMALE.4 2.867,8.137 3.004,8.047 3.139,7.913 3.55,7.501 3.55,7.201 4.755,5.997 8.747,5.997 v1(9.625,6.875)
VBAT_HALF: FEMALE-BOARD-HEADER.4 MCU.40 | length 6.9
  Top Signal w0.13: FEMALE-BOARD-HEADER.4@11.943,8.85 FEMALE-BOARD-HEADER.4
  Top Signal w0.25: MCU.40 6,8.7 6,8.999 6.476,9.475 10.7,9.475 11.325,8.85 FEMALE-BOARD-HEADER.4@11.943,8.85
VCC_3.3: C_INT1.1 FEMALE-BOARD-HEADER.2 MCU.26 PROG-CON-FEMALE.2 RHD2132.13 RHD2132.26 RHD2132.31 | length 9.4
  Top Signal w0.13: RHD2132.31 3.807,11.593 3.978,11.422 v1(4.025,11.422)
  Top Signal w0.25: v1(1.55,20.225) 1.55,20.976 1.999,21.425 2.814,21.425 3.307,20.932 RHD2132.13 ; v1(7.375,11.475) 7.423,11.427 7.423,11.276 C_INT1.1 ; MCU.26 10.25,6.225 v1(10.875,6.85) FEMALE-BOARD-HEADER.2
  Bottom Layer w0.25: v2(1.225,7.625) 1.305,7.625 1.858,7.072 2.457,7.072 2.485,7.1 PROG-CON-FEMALE.2@2.485,7.11
  other v1: 2.007,14.122
pads on no net: MCU.2 MCU.3 MCU.4 MCU.5 MCU.6 MCU.8 MCU.9 MCU.10 MCU.11 MCU.12 MCU.13 MCU.15 MCU.17 MCU.19 MCU.27 MCU.29 MCU.32 MCU.33 MCU.34 MCU.35 MCU.36 MCU.37 MCU.39 MCU.41 MCU.43 MCU.45 MCU.47 MCU.48 MCU.49 MCU.50 MCU.54 MCU.56 MCU.57 MCU.58 MCU.60 MCU.61 MCU.62 MCU.63 MCU.64 MCU.65 MCU.66 MCU.67 MCU.68 MCU.69 MCU.70 MCU.71 MCU.72 MCU.73 MCU.74 MCU.75 MCU.76 MCU.77 MCU.78 PROG-CON-FEMALE.5 PROG-CON-FEMALE.6 RHD2132.14 RHD2132.15 RHD2132.16 RHD2132.18 RHD2132.20 RHD2132.22 RHD2132.24 RHD2132.27 RHD2132.33 RHD2132.34 RHD2132.35 RHD2132.36 RHD2132.37 RHD2132.38 RHD2132.39 RHD2132.40 RHD2132.41 RHD2132.42 RHD2132.43 RHD2132.44 RHD2132.45 RHD2132.46 RHD2132.47 RHD2132.48 RHD2132.49

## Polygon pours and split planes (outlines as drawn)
VCC_3.3 on Layer 2 - VCC "VCC_3.3" (solid, remove dead copper, shelved, pour order 4): 0.317,22.305 0.317,24.204 cw(c1.496,24.204) 1.496,25.383 10.619,25.383 cw(c10.619,24.157) 11.845,24.157 11.845,16.003 ccw(c12.831,16.003) 12.831,15.018 cw(c12.831,13.78) 14.069,13.78 14.069,4.904 0.291,4.919 0.317,22.303
GND on Layer 3 - GND "GND " (solid, remove dead copper, shelved, pour order 5): 0.317,22.305 0.317,24.203 cw(c1.496,24.203) 1.496,25.382 10.619,25.382 cw(c10.619,24.156) 11.845,24.156 11.845,16.003 ccw(c12.831,16.003) 12.831,15.017 cw(c12.831,13.779) 14.069,13.779 14.069,4.903 0.291,4.919 0.317,22.302
GND on Top Signal "GND " (solid, remove dead copper, shelved, pour order 7): 0.317,22.305 0.317,24.203 cw(c1.496,24.203) 1.496,25.382 10.619,25.382 cw(c10.619,24.156) 11.845,24.156 11.845,16.003 ccw(c12.831,16.003) 12.831,15.017 cw(c12.831,13.779) 14.069,13.779 14.069,4.903 0.291,4.919 0.317,22.302
GND on Bottom Layer "GND " (solid, remove dead copper, shelved, pour order 6): 0.317,22.305 0.317,24.203 cw(c1.496,24.203) 1.496,25.382 10.619,25.382 cw(c10.619,24.156) 11.845,24.156 11.845,16.003 ccw(c12.831,16.003) 12.831,15.017 cw(c12.831,13.779) 14.069,13.779 14.069,4.903 0.291,4.919 0.317,22.302

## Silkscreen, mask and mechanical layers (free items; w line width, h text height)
Flex Top Overlay:
  text "1:GND" at 11.445,4.005 h0.3 r90
Bottom Overlay:
  drawing of 5 lines, arcs and shapes, not listed
  text "CH1" at 3.808,18.1 h0.4
  text "REF" at 9.283,18.075 h0.4
  text "GND" at 3.808,16.445 h0.4
  text "REF" at 9.283,16.42 h0.4
  text "GND" at 3.808,14.695 h0.4
  text "CH1" at 9.283,14.67 h0.4
  text "GND" at 4.325,11.975 h0.4
  text "CH1" at 6.5,11.975 h0.4
  text "REF" at 8.8,11.975 h0.4
  text "MARM-V001" at 11.025,2.05 h0.8
  text "Bottom Board" at 11.075,1.075 h0.5
Mechanical 1:
  lines w0.15: -0.924,1.722 ccw(c0.346,1.722) 0.346,0.452 13.906,0.452 ccw(c13.906,1.722) 15.176,1.722 15.176,10.077 15.176,12.922 15.176,26.782 ccw(c13.906,26.782) 13.906,28.052 0.346,28.052 ccw(c0.346,26.782) -0.924,26.782 -0.924,1.722 ; 0.225,1.695 ccw(c1.495,1.695) 1.495,0.425 1.745,0.425 10.405,0.425 ccw(c10.405,1.695) 11.675,1.695 11.675,2.23 cw(c12.945,2.23) 12.945,3.5 ccw(c12.945,4.68) 14.125,4.68 14.125,9.825 14.125,13.83 ccw(c12.855,13.83) 12.855,15.1 cw(c12.855,16.03) 11.925,16.03 11.925,16.28 11.925,23.955 11.925,24.205 ccw(c10.655,24.205) 10.655,25.475 1.5,25.5 1.495,25.5 ccw(c1.495,24.23) 0.225,24.23 0.225,23.955 0.225,1.695 ; 11.026,5.352 11.026,13.352 13.526,13.352 13.526,5.352 11.026,5.352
